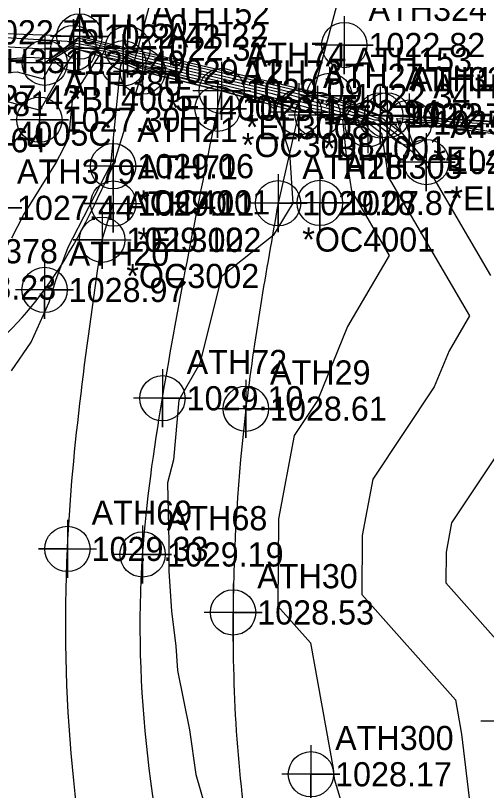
# Model space of a CAD drawing. Extents: x 1213164 to 1213550, y 766120 to 766870.
# Drawn here: x 1213304.4 to 1213353.1, y 766399.6 to 766479.8 of the extents above; entities that cross this region are included whole.
import ezdxf

# ---------------------------------------------------------------- set-up
doc = ezdxf.new("R2010")
doc.units = 0
for name, color, linetype in [('Default', 7, 'Continuous'), ('Exist DTM Breakline', 7, 'Continuous'), ('Exist DTM Breakline Cogo Comment', 7, 'Continuous'), ('Exist DTM Breakline Cogo Elevation', 7, 'Continuous'), ('Exist DTM Breakline Cogo Number', 7, 'Continuous'), ('Exist DTM Breakline Cogo Point CELL', 7, 'Continuous'), ('Exist DTM Crownline', 7, 'Continuous'), ('Exist DTM Crownline Cogo Comment', 7, 'Continuous'), ('Exist DTM Crownline Cogo Elevation', 7, 'Continuous'), ('Exist DTM Crownline Cogo Number', 7, 'Continuous'), ('Exist DTM Crownline Cogo Point CELL', 7, 'Continuous'), ('Exist DTM Drainline Cogo Elevation', 7, 'Continuous'), ('Exist DTM Drainline Cogo Number', 7, 'Continuous'), ('Exist DTM Drainline Cogo Point CELL', 7, 'Continuous'), ('Exist DTM Regular Point CELL', 7, 'Continuous'), ('Exist DTM Regular Point Cogo Comment', 7, 'Continuous'), ('Exist DTM Regular Point Cogo Elevation', 7, 'Continuous'), ('Exist DTM Regular Point Cogo Number', 7, 'Continuous'), ('Exist DTM Regular Point Underwater CELL', 7, 'Continuous'), ('Exist DTM Regular Point Underwater Cogo Elevation', 7, 'Continuous'), ('Exist DTM Regular Point Underwater Cogo Number', 7, 'Continuous'), ('Exist Hydro Stream or Body of Water', 7, 'Continuous'), ('Exist Roads EOP', 7, 'Continuous'), ('Exist Roads EOP Cogo Point CELL', 7, 'Continuous'), ('Exist Roads EOT', 7, 'Continuous'), ('Exist Roads EOT Cogo Comment', 7, 'Continuous'), ('Exist Roads EOT Cogo Elevation', 7, 'Continuous'), ('Exist Roads EOT Cogo Number', 7, 'Continuous'), ('Exist Roads EOT Cogo Point CELL', 7, 'Continuous'), ('Exist Structure Major Bridge WW Cogo Point CELL', 7, 'Continuous'), ('Exist Structure Major Deck Tunnel Box Culvert', 7, 'Continuous')]:
    doc.layers.add(name, color=color, linetype=linetype)

msp = doc.modelspace()

# ---------------------------------------------------------------- linework, layer by layer
at = {"layer": 'Default'}
for points in [[(1213299.207, 766477.781), (1213310.305, 766477.117), (1213310.903, 766477.472), (1213311.38, 766477.387), (1213315.92, 766476.23), (1213316.107, 766476.153), (1213316.874, 766475.964), (1213335.76, 766471.527), (1213336.532, 766471.309), (1213336.72, 766471.273), (1213337.373, 766471.09), (1213342.046, 766469.416), (1213342.729, 766469.43), (1213343.065, 766469.172), (1213342.98, 766469.415), (1213359.97, 766468.473)], [(1213297.517, 766474.821), (1213305.774, 766475.477), (1213307.958, 766475.347), (1213310.62, 766476.932), (1213312.747, 766476.55), (1213315.784, 766475.776), (1213316.568, 766475.452), (1213319.773, 766474.663), (1213332.456, 766471.684), (1213335.574, 766470.802), (1213336.335, 766470.656), (1213338.972, 766469.915), (1213341.48, 766469.016), (1213341.847, 766469.024), (1213345.644, 766466.108), (1213344.676, 766468.862), (1213348.091, 766468.673), (1213359.464, 766466.862)], [(1213302.491, 766476.629), (1213309.132, 766476.232), (1213310.761, 766477.202), (1213312.064, 766476.969), (1213315.852, 766476.003), (1213316.337, 766475.803), (1213318.323, 766475.313), (1213334.108, 766471.606), (1213336.053, 766471.056), (1213336.528, 766470.965), (1213338.172, 766470.502), (1213341.763, 766469.216), (1213342.288, 766469.227), (1213344.355, 766467.64), (1213343.828, 766469.139), (1213354.03, 766468.573)], [(1213297.125, 766473.377), (1213304.52, 766473.965), (1213307.231, 766473.253), (1213308.477, 766475.47), (1213310.478, 766476.662), (1213313.43, 766476.132), (1213315.717, 766475.549), (1213316.798, 766475.102), (1213321.222, 766474.012), (1213330.803, 766471.762), (1213335.095, 766470.549), (1213336.142, 766470.348), (1213339.771, 766469.328), (1213341.197, 766468.817), (1213341.405, 766468.821), (1213346.67, 766464.778), (1213346.7, 766464.579), (1213353.528, 766452.918)], [(1213298.906, 766472.106), (1213306.934, 766469.999), (1213309.324, 766474.252), (1213310.651, 766476.335), (1213314.113, 766475.714), (1213315.649, 766475.323), (1213317.028, 766474.752), (1213322.672, 766473.362), (1213329.151, 766471.84), (1213334.616, 766470.295), (1213335.95, 766470.039), (1213340.571, 766468.74), (1213340.914, 766468.617), (1213340.964, 766468.618), (1213342.231, 766467.645), (1213342.919, 766463.126), (1213351.349, 766448.729), (1213349.23, 766445.13), (1213347.71, 766441.381), (1213341.348, 766431.84), (1213340.248, 766426.022), (1213340.207, 766419.908), (1213349.894, 766409.005), (1213350.533, 766405.472), (1213351.414, 766397.98)], [(1213303.969, 766456.805), (1213305.175, 766459.164), (1213308.506, 766464.447), (1213309.877, 766467.108), (1213310.314, 766471.357), (1213313.025, 766475.613), (1213314.796, 766475.296), (1213315.582, 766475.096), (1213317.259, 766474.402), (1213324.121, 766472.711), (1213327.499, 766471.918), (1213334.137, 766470.042), (1213335.757, 766469.731), (1213338.203, 766469.043), (1213338.636, 766464.967), (1213339.137, 766461.674), (1213343.052, 766454.988), (1213338.727, 766447.64), (1213335.623, 766439.987), (1213333.203, 766436.357), (1213331.575, 766427.748), (1213331.515, 766418.699), (1213334.883, 766414.908), (1213337.23, 766401.929), (1213337.359, 766400.83), (1213340.928, 766389.024)], [(1213303.947, 766443.062), (1213305.989, 766446.009), (1213307.853, 766450.16), (1213308.53, 766452.427), (1213309.815, 766455.83), (1213310.839, 766457.834), (1213310.883, 766457.905), (1213314.216, 766464.374), (1213315.278, 766474.701), (1213315.399, 766474.892), (1213315.479, 766474.878), (1213315.514, 766474.869), (1213317.489, 766474.052), (1213325.571, 766472.061), (1213325.847, 766471.996), (1213330.535, 766470.671), (1213331.33, 766469.903), (1213332.729, 766465.599), (1213333.058, 766460.393), (1213331.017, 766457.04), (1213325.683, 766452.811), (1213323.457, 766443.809), (1213321.279, 766439.997), (1213320.708, 766433.837), (1213320.088, 766431.45), (1213320.217, 766425.326), (1213320.24, 766422.313), (1213320.511, 766418.177), (1213320.964, 766414.58), (1213321.12, 766412.065), (1213322.375, 766405.909), (1213323.042, 766401.286), (1213323.994, 766397.938)], [(1213359.279, 766441.998), (1213349.493, 766427.323), (1213348.921, 766424.297), (1213348.9, 766421.116), (1213356.538, 766412.518)]]:
    msp.add_lwpolyline(points, dxfattribs=at)
at = {"layer": 'Exist DTM Breakline'}
for p, q in [((1213315.511, 766474.858), (1213310.354, 766476.425)), ((1213335.628, 766469.524), (1213340.824, 766468.554))]:
    msp.add_line(p, q, dxfattribs=at)
for points in [[(1213307.383, 766474.913), (1213310.985, 766477.629)], [(1213342.815, 766469.469), (1213346.874, 766464.646)], [(1213525.393, 766207.467), (1213482.007, 766225.047), (1213449.305, 766226.194), (1213431.701, 766256.624), (1213419.176, 766304.878), (1213413.481, 766348.824), (1213382.307, 766373.433), (1213372.705, 766395.689), (1213369.183, 766434.583), (1213366.951, 766449.615), (1213359.429, 766466.809), (1213345.103, 766468.723)]]:
    msp.add_lwpolyline(points, dxfattribs=at)
at = {"layer": 'Exist DTM Breakline Cogo Point CELL'}
for points in [[(1213310.985, 766480.629), (1213310.985, 766474.629), (1213310.985, 766477.629), (1213313.985, 766477.629), (1213307.985, 766477.629)], [(1213315.962, 766479.373), (1213315.962, 766473.373), (1213315.962, 766476.373), (1213318.962, 766476.373), (1213312.962, 766476.373)], [(1213307.383, 766477.913), (1213307.383, 766471.913), (1213307.383, 766474.913), (1213310.383, 766474.913), (1213304.383, 766474.913)], [(1213336.847, 766474.476), (1213336.847, 766468.476), (1213336.847, 766471.476), (1213339.847, 766471.476), (1213333.847, 766471.476)], [(1213342.815, 766472.469), (1213342.815, 766466.469), (1213342.815, 766469.469), (1213345.815, 766469.469), (1213339.815, 766469.469)], [(1213345.103, 766471.723), (1213345.103, 766465.723), (1213345.103, 766468.723), (1213348.103, 766468.723), (1213342.103, 766468.723)], [(1213346.874, 766467.646), (1213346.874, 766461.646), (1213346.874, 766464.646), (1213349.874, 766464.646), (1213343.874, 766464.646)], [(1213355.508, 766409.797), (1213355.508, 766403.797), (1213355.508, 766406.797), (1213358.508, 766406.797), (1213352.508, 766406.797)]]:
    msp.add_lwpolyline(points, dxfattribs=at)
for centre in [(1213310.985, 766477.629), (1213315.962, 766476.373), (1213307.383, 766474.913), (1213336.847, 766471.476), (1213342.815, 766469.469), (1213345.103, 766468.723), (1213346.874, 766464.646)]:
    msp.add_circle(centre, 2.344, dxfattribs=at)
at = {"layer": 'Exist DTM Crownline'}
msp.add_line((1213325.279, 766470.159), (1213325.7, 766472.003), dxfattribs=at)
msp.add_spline([(1213364.822, 766294.526), (1213349.913, 766319.907), (1213339.177, 766339.489), (1213331.697, 766355.273), (1213321.978, 766382.664), (1213317.523, 766424.054), (1213319.575, 766440.21), (1213325.279, 766470.159)], degree=3, dxfattribs=at)
at = {"layer": 'Exist DTM Crownline Cogo Point CELL'}
for points in [[(1213325.7, 766475.003), (1213325.7, 766469.003), (1213325.7, 766472.003), (1213328.7, 766472.003), (1213322.7, 766472.003)], [(1213325.279, 766473.159), (1213325.279, 766467.159), (1213325.279, 766470.159), (1213328.279, 766470.159), (1213322.279, 766470.159)], [(1213319.575, 766443.21), (1213319.575, 766437.21), (1213319.575, 766440.21), (1213322.575, 766440.21), (1213316.575, 766440.21)], [(1213317.523, 766427.054), (1213317.523, 766421.054), (1213317.523, 766424.054), (1213320.523, 766424.054), (1213314.523, 766424.054)]]:
    msp.add_lwpolyline(points, dxfattribs=at)
for centre in [(1213325.7, 766472.003), (1213325.279, 766470.159), (1213319.575, 766440.21), (1213317.523, 766424.054)]:
    msp.add_circle(centre, 2.344, dxfattribs=at)
at = {"layer": 'Exist DTM Drainline Cogo Point CELL'}
msp.add_lwpolyline([(1213342.113, 766472.463), (1213342.113, 766466.463), (1213342.113, 766469.463), (1213345.113, 766469.463), (1213339.113, 766469.463)], dxfattribs=at)
msp.add_circle((1213342.113, 766469.463), 2.344, dxfattribs=at)
at = {"layer": 'Exist DTM Regular Point CELL'}
for points in [[(1213306.844, 766472.02), (1213306.844, 766466.02), (1213306.844, 766469.02), (1213309.844, 766469.02), (1213303.844, 766469.02)], [(1213335.859, 766463.414), (1213335.859, 766457.414), (1213335.859, 766460.414), (1213338.859, 766460.414), (1213332.859, 766460.414)], [(1213302.014, 766462.906), (1213302.014, 766456.906), (1213302.014, 766459.906), (1213305.014, 766459.906), (1213299.014, 766459.906)], [(1213334.942, 766404.32), (1213334.942, 766398.32), (1213334.942, 766401.32), (1213337.942, 766401.32), (1213331.942, 766401.32)]]:
    msp.add_lwpolyline(points, dxfattribs=at)
for centre in [(1213306.844, 766469.02), (1213335.859, 766460.414), (1213334.942, 766401.32)]:
    msp.add_circle(centre, 2.344, dxfattribs=at)
at = {"layer": 'Exist DTM Regular Point Underwater CELL'}
msp.add_lwpolyline([(1213338.392, 766479.744), (1213338.392, 766473.744), (1213338.392, 766476.744), (1213341.392, 766476.744), (1213335.392, 766476.744)], dxfattribs=at)
msp.add_circle((1213338.392, 766476.744), 2.344, dxfattribs=at)
at = {"layer": 'Exist Hydro Stream or Body of Water'}
for points in [[(1213342.815, 766469.469), (1213342.113, 766469.463), (1213336.847, 766471.476), (1213315.962, 766476.373), (1213310.985, 766477.629), (1213298.396, 766478.065)], [(1213528.184, 766208.953), (1213518.126, 766232.156), (1213482.648, 766228.638), (1213450.602, 766228.856), (1213434.621, 766256.535), (1213425.001, 766305.328), (1213420.53, 766356.324), (1213385.097, 766376.623), (1213376.318, 766397.22), (1213374.288, 766436.335), (1213371.57, 766451.854), (1213360.534, 766468.464), (1213342.815, 766469.469)]]:
    msp.add_lwpolyline(points, dxfattribs=at)
at = {"layer": 'Exist Roads EOP'}
for p, q in [((1213314.463, 766464.218), (1213317.516, 766474.011)), ((1213333.686, 766469.803), (1213331.542, 766460.381))]:
    msp.add_line(p, q, dxfattribs=at)
msp.add_lwpolyline([(1213317.516, 766474.011), (1213325.7, 766472.003), (1213333.686, 766469.803)], dxfattribs=at)
for points in [[(1213254.792, 766432.471), (1213265.89, 766431.056), (1213288.934, 766436.739), (1213307.368, 766451.415), (1213314.463, 766464.218)], [(1213331.542, 766460.381), (1213328.202, 766439.131), (1213326.882, 766418.055), (1213328.894, 766392.003), (1213339.56, 766359.268), (1213347.201, 766343.262), (1213357.639, 766324.019), (1213372.578, 766298.933)], [(1213169.012, 766424.202), (1213197.361, 766422.679), (1213222.732, 766418.674), (1213259.828, 766408.159), (1213283.389, 766394.331), (1213303.908, 766375.84), (1213322.371, 766351.308)]]:
    msp.add_spline(points, degree=3, dxfattribs=at)
at = {"layer": 'Exist Roads EOP Cogo Point CELL'}
for points in [[(1213317.516, 766477.011), (1213317.516, 766471.011), (1213317.516, 766474.011), (1213320.516, 766474.011), (1213314.516, 766474.011)], [(1213333.686, 766472.803), (1213333.686, 766466.803), (1213333.686, 766469.803), (1213336.686, 766469.803), (1213330.686, 766469.803)], [(1213314.463, 766467.218), (1213314.463, 766461.218), (1213314.463, 766464.218), (1213317.463, 766464.218), (1213311.463, 766464.218)], [(1213331.542, 766463.381), (1213331.542, 766457.381), (1213331.542, 766460.381), (1213334.542, 766460.381), (1213328.542, 766460.381)], [(1213307.368, 766454.415), (1213307.368, 766448.415), (1213307.368, 766451.415), (1213310.368, 766451.415), (1213304.368, 766451.415)], [(1213328.202, 766442.131), (1213328.202, 766436.131), (1213328.202, 766439.131), (1213331.202, 766439.131), (1213325.202, 766439.131)], [(1213326.882, 766421.055), (1213326.882, 766415.055), (1213326.882, 766418.055), (1213329.882, 766418.055), (1213323.882, 766418.055)]]:
    msp.add_lwpolyline(points, dxfattribs=at)
for centre in [(1213317.516, 766474.011), (1213333.686, 766469.803), (1213314.463, 766464.218), (1213331.542, 766460.381), (1213307.368, 766451.415), (1213328.202, 766439.131), (1213326.882, 766418.055)]:
    msp.add_circle(centre, 2.344, dxfattribs=at)
at = {"layer": 'Exist Roads EOT'}
msp.add_line((1213313.333, 766456.611), (1213314.486, 766460.34), dxfattribs=at)
msp.add_spline([(1213322.777, 766353.555), (1213314.072, 766379.917), (1213309.739, 766424.629), (1213313.333, 766456.611)], degree=3, dxfattribs=at)
at = {"layer": 'Exist Roads EOT Cogo Point CELL'}
for points in [[(1213314.486, 766463.34), (1213314.486, 766457.34), (1213314.486, 766460.34), (1213311.486, 766460.34), (1213317.486, 766460.34)], [(1213313.333, 766459.611), (1213313.333, 766453.611), (1213313.333, 766456.611), (1213310.333, 766456.611), (1213316.333, 766456.611)], [(1213309.739, 766427.629), (1213309.739, 766421.629), (1213309.739, 766424.629), (1213306.739, 766424.629), (1213312.739, 766424.629)]]:
    msp.add_lwpolyline(points, dxfattribs=at)
for centre in [(1213314.486, 766460.34), (1213313.333, 766456.611), (1213309.739, 766424.629)]:
    msp.add_circle(centre, 2.344, dxfattribs=at)
at = {"layer": 'Exist Structure Major Bridge WW Cogo Point CELL'}
for points in [[(1213307.354, 766476.425), (1213313.354, 766476.425), (1213310.354, 766476.425), (1213310.354, 766479.425), (1213310.354, 766473.425)], [(1213312.511, 766474.858), (1213318.511, 766474.858), (1213315.511, 766474.858), (1213315.511, 766477.858), (1213315.511, 766471.858)], [(1213332.628, 766469.524), (1213338.628, 766469.524), (1213335.628, 766469.524), (1213335.628, 766472.524), (1213335.628, 766466.524)], [(1213337.824, 766468.554), (1213343.824, 766468.554), (1213340.824, 766468.554), (1213340.824, 766471.554), (1213340.824, 766465.554)]]:
    msp.add_lwpolyline(points, dxfattribs=at)
for centre in [(1213310.354, 766476.425), (1213315.511, 766474.858), (1213335.628, 766469.524), (1213340.824, 766468.554)]:
    msp.add_circle(centre, 2.344, dxfattribs=at)
at = {"layer": 'Exist Structure Major Deck Tunnel Box Culvert'}
msp.add_lwpolyline([(1213334.645, 766469.793), (1213316.583, 766474.725), (1213327.014, 766513.184), (1213344.974, 766508.526), (1213334.645, 766469.793)], dxfattribs=at)

# ---------------------------------------------------------------- texts
at = {"layer": 'Exist DTM Breakline Cogo Comment'}
for s, p in [('*BL4005', (1213309.883, 766469.913)), ('*BL4005C', (1213299.071, 766466.333)), ('*EL4005D', (1213347.603, 766463.723)), ('*EL4005', (1213349.374, 766459.646))]:
    msp.add_text(s, height=2.5, dxfattribs=at).set_placement(p)
at = {"layer": 'Exist DTM Breakline Cogo Elevation'}
for s, p in [('1022.42', (1213313.485, 766476.379)), ('1022.37', (1213318.462, 766475.123)), ('1025.49', (1213309.883, 766473.663)), ('1027.42', (1213299.071, 766470.083)), ('1022.34', (1213339.347, 766470.226)), ('1022.81', (1213345.315, 766468.219)), ('1025.50', (1213347.603, 766467.473)), ('1025.95', (1213349.374, 766463.396))]:
    msp.add_text(s, height=2.5, dxfattribs=at).set_placement(p)
at = {"layer": 'Exist DTM Breakline Cogo Number'}
for s, p in [('ATH152', (1213318.462, 766478.873)), ('ATH150', (1213309.883, 766477.413)), ('ATH351', (1213299.071, 766473.833)), ('ATH153', (1213339.347, 766473.976)), ('ATH154', (1213345.315, 766471.969)), ('ATH321', (1213347.603, 766471.223)), ('ATH155', (1213349.374, 766467.146))]:
    msp.add_text(s, height=2.5, dxfattribs=at).set_placement(p)
at = {"layer": 'Exist DTM Crownline Cogo Comment'}
for s, p in [('*EL3008', (1213328.2, 766467.003)), ('*OC3008', (1213327.779, 766465.159))]:
    msp.add_text(s, height=2.5, dxfattribs=at).set_placement(p)
at = {"layer": 'Exist DTM Crownline Cogo Elevation'}
for s, p in [('1029.09', (1213328.2, 766470.753)), ('1029.15', (1213327.779, 766468.909)), ('1029.10', (1213322.075, 766438.96)), ('1029.19', (1213320.023, 766422.804))]:
    msp.add_text(s, height=2.5, dxfattribs=at).set_placement(p)
at = {"layer": 'Exist DTM Crownline Cogo Number'}
for s, p in [('ATH74', (1213328.2, 766474.503)), ('ATH73', (1213327.779, 766472.659)), ('ATH72', (1213322.075, 766442.71)), ('ATH68', (1213320.023, 766426.554))]:
    msp.add_text(s, height=2.5, dxfattribs=at).set_placement(p)
at = {"layer": 'Exist DTM Drainline Cogo Elevation'}
for s, p in [('1022.75', (1213300.896, 766476.815)), ('1022.76', (1213344.613, 766468.213))]:
    msp.add_text(s, height=2.5, dxfattribs=at).set_placement(p)
at = {"layer": 'Exist DTM Drainline Cogo Number'}
msp.add_text('ATH322', height=2.5, dxfattribs=at).set_placement((1213344.613, 766471.963))
at = {"layer": 'Exist DTM Regular Point Cogo Comment'}
for s, p in [('*EL4001', (1213320.016, 766469.011)), ('*BL4001', (1213336.186, 766464.803)), ('*OC4001', (1213316.963, 766459.218)), ('*OC4001', (1213334.042, 766455.381))]:
    msp.add_text(s, height=2.5, dxfattribs=at).set_placement(p)
at = {"layer": 'Exist DTM Regular Point Cogo Elevation'}
for s, p in [('1029.12', (1213320.016, 766472.761)), ('1028.94', (1213336.186, 766468.553)), ('1027.30', (1213309.344, 766467.77)), ('1027.64', (1213295.477, 766465.646)), ('1029.06', (1213316.963, 766462.968)), ('1029.07', (1213334.042, 766459.131)), ('1028.87', (1213338.359, 766459.164)), ('1027.44', (1213304.514, 766458.656)), ('1028.23', (1213296.487, 766450.417)), ('1028.97', (1213309.868, 766450.165)), ('1028.61', (1213330.702, 766437.881)), ('1028.53', (1213329.382, 766416.805)), ('1028.17', (1213337.442, 766400.07))]:
    msp.add_text(s, height=2.5, dxfattribs=at).set_placement(p)
at = {"layer": 'Exist DTM Regular Point Cogo Number'}
for s, p in [('ATH22', (1213320.016, 766476.511)), ('ATH27', (1213336.186, 766472.303)), ('ATH380', (1213309.344, 766471.52)), ('ATH381', (1213295.477, 766469.396)), ('ATH21', (1213316.963, 766466.718)), ('ATH379', (1213304.514, 766462.406)), ('ATH28', (1213334.042, 766462.881)), ('ATH303', (1213338.359, 766462.914)), ('ATH378', (1213296.487, 766454.167)), ('ATH20', (1213309.868, 766453.915)), ('ATH29', (1213330.702, 766441.631)), ('ATH30', (1213329.382, 766420.555)), ('ATH300', (1213337.442, 766403.82))]:
    msp.add_text(s, height=2.5, dxfattribs=at).set_placement(p)
at = {"layer": 'Exist DTM Regular Point Underwater Cogo Elevation'}
msp.add_text('1022.82', height=2.5, dxfattribs=at).set_placement((1213340.892, 766475.494))
at = {"layer": 'Exist DTM Regular Point Underwater Cogo Number'}
msp.add_text('ATH324', height=2.5, dxfattribs=at).set_placement((1213340.892, 766479.244))
at = {"layer": 'Exist Roads EOT Cogo Comment'}
for s, p in [('*EL3002', (1213316.986, 766455.34)), ('*OC3002', (1213315.833, 766451.611))]:
    msp.add_text(s, height=2.5, dxfattribs=at).set_placement(p)
at = {"layer": 'Exist Roads EOT Cogo Elevation'}
for s, p in [('1029.11', (1213316.986, 766459.09)), ('1029.12', (1213315.833, 766455.361)), ('1029.33', (1213312.239, 766423.379))]:
    msp.add_text(s, height=2.5, dxfattribs=at).set_placement(p)
at = {"layer": 'Exist Roads EOT Cogo Number'}
for s, p in [('ATH71', (1213316.986, 766462.84)), ('ATH70', (1213315.833, 766459.111)), ('ATH69', (1213312.239, 766427.129))]:
    msp.add_text(s, height=2.5, dxfattribs=at).set_placement(p)

doc.saveas('drawing.dxf')
